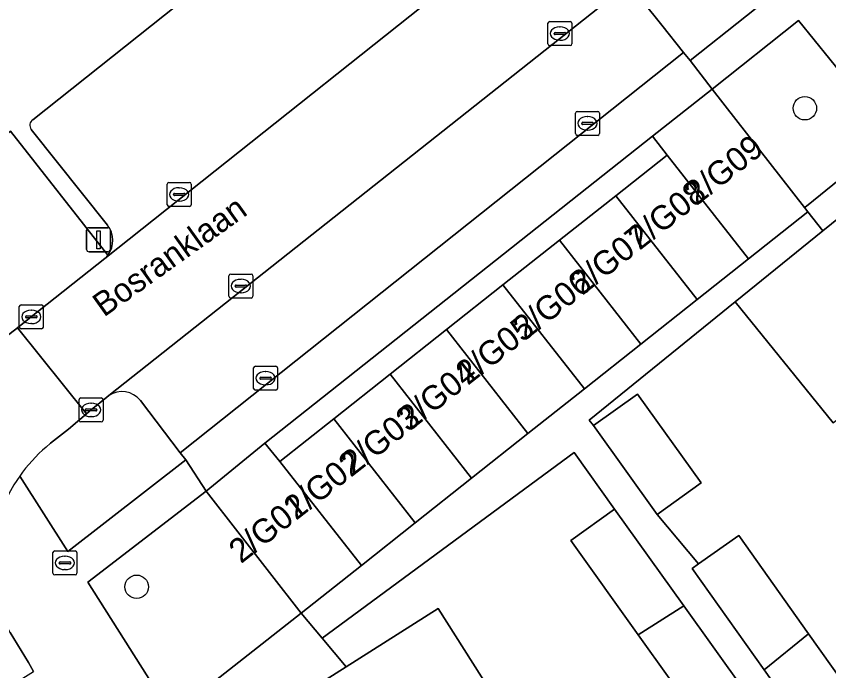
# Model space of a CAD drawing. Extents: x 162344 to 162869, y 381217 to 381818.
# Drawn here: x 162476.05 to 162509.92, y 381652.77 to 381680.06 of the extents above; entities that cross this region are included whole.
import ezdxf

# ---------------------------------------------------------------- set-up
doc = ezdxf.new("R2010")
doc.units = 0
for name, color, linetype in [('IMGEO_Boom', 7, 'Continuous'), ('IMGEO_Brandkraan', 7, 'Continuous'), ('IMGEO_Erf', 7, 'Continuous'), ('IMGEO_Groenvoorziening', 7, 'Continuous'), ('IMGEO_Kolk', 7, 'Continuous'), ('IMGEO_Lichtmast', 7, 'Continuous'), ('IMGEO_Openbare_ruimte_label', 7, 'Continuous'), ('IMGEO_Pand', 7, 'Continuous'), ('IMGEO_Pand_nummerreeks', 7, 'Continuous'), ('IMGEO_Parkeervlak_open', 7, 'Continuous'), ('IMGEO_Rijbaan_lokaal_open', 7, 'Continuous'), ('IMGEO_Voetpad_open', 7, 'Continuous')]:
    doc.layers.add(name, color=color, linetype=linetype)

msp = doc.modelspace()

# ---------------------------------------------------------------- linework, layer by layer
at = {"layer": 'IMGEO_Boom'}
for centre in [(162508.924, 381676.221), (162481.072, 381656.273)]:
    msp.add_circle(centre, 0.489, dxfattribs=at)
at = {"layer": 'IMGEO_Brandkraan'}
for p, q in [((162477.581, 381656.845), (162477.581, 381657.697)), ((162477.656, 381657.771), (162478.508, 381657.771)), ((162478.582, 381657.697), (162478.582, 381656.845)), ((162477.84, 381657.265), (162477.84, 381657.277)), ((162477.883, 381657.314), (162478.281, 381657.314)), ((162478.069, 381657.551), (162478.094, 381657.551)), ((162478.324, 381657.277), (162478.324, 381657.265)), ((162478.278, 381657.228), (162477.88, 381657.228)), ((162478.092, 381656.991), (162478.067, 381656.991)), ((162478.508, 381656.771), (162477.656, 381656.771))]:
    msp.add_line(p, q, dxfattribs=at)
for points in [[(162477.581, 381656.845), (162477.581, 381657.697)], [(162477.656, 381657.771), (162478.508, 381657.771)], [(162478.582, 381657.697), (162478.582, 381656.845)], [(162478.508, 381656.771), (162477.656, 381656.771)]]:
    msp.add_lwpolyline(points, dxfattribs=at)
for centre, radius, start, end in [((162477.658, 381657.695), 0.0765, 91.552, 178.448), ((162477.658, 381657.695), 0.0765, 91.552, 178.448), ((162478.506, 381657.695), 0.0765, 1.552, 88.448), ((162478.506, 381657.695), 0.0765, 1.552, 88.448), ((162477.88, 381657.274), 0.0403, 85.8775, 175.7526), ((162477.877, 381657.264), 0.0366, 178.938, 274.7102), ((162478.281, 381657.271), 0.043, 264.8664, 352.4533), ((162478.285, 381657.276), 0.0386, 1.7309, 96.639), ((162477.658, 381656.847), 0.0765, 181.552, 268.448), ((162477.658, 381656.847), 0.0765, 181.552, 268.448), ((162478.506, 381656.847), 0.0765, 271.552, 358.448), ((162478.506, 381656.847), 0.0765, 271.552, 358.448)]:
    msp.add_arc(centre, radius, start, end, dxfattribs=at)
for centre, major_axis, ratio, start_param, end_param in [((162478.068, 381657.271), (-0.387, 0.002), 0.722429, 4.712389, 7.853982), ((162478.093, 381657.271), (-0.39, 0.002), 0.717154, 1.570796, 4.712389)]:
    msp.add_ellipse(centre, major_axis=major_axis, ratio=ratio, start_param=start_param, end_param=end_param, dxfattribs=at)
at = {"layer": 'IMGEO_Erf'}
msp.add_lwpolyline([(162496.342, 381668.856), (162498.692, 381670.716), (162501.043, 381672.576), (162503.181, 381674.267), (162502.572, 381675.054), (162486.414, 381662.265), (162487.042, 381661.499), (162489.29, 381663.278), (162491.641, 381665.137), (162493.991, 381666.996)], close=True, dxfattribs=at)
for points in [[(162510.099, 381663.114), (162506.026, 381668.154), (162499.933, 381663.224), (162500.114, 381662.996), (162501.945, 381664.309), (162504.599, 381660.606), (162502.768, 381659.294), (162504.496, 381657.227), (162506.17, 381658.416), (162509.083, 381654.315), (162511.58, 381650.8), (162509.855, 381649.575), (162511.736, 381646.935)], [(162510.377, 381642.133), (162507.288, 381646.468), (162509.19, 381647.823), (162506.326, 381651.913), (162504.565, 381650.654), (162501.976, 381654.276), (162499.167, 381658.207), (162500.996, 381659.515), (162499.313, 381661.868), (162488.804, 381654.132), (162489.805, 381652.936), (162493.635, 381655.366), (162496.526, 381650.81), (162500.523, 381644.51), (162504.431, 381638.351), (162507.26, 381633.892), (162509.92, 381629.7), (162513.898, 381623.43)]]:
    msp.add_lwpolyline(points, dxfattribs=at)
at = {"layer": 'IMGEO_Groenvoorziening'}
for points in [[(162502.172, 381680.676), (162502.959, 381679.681), (162503.867, 381678.548), (162504.138, 381678.21), (162508.84, 381681.944)], [(162476.197, 381660.891), (162478.205, 381657.739), (162483.121, 381661.563), (162482.891, 381661.863), (162481.227, 381664.037)], [(162479.911, 381664.241), (162479.827, 381664.177), (162479.173, 381663.648), (162478.985, 381663.489), (162478.231, 381662.85), (162477.479, 381662.26), (162477.304, 381662.098)]]:
    msp.add_lwpolyline(points, dxfattribs=at)
for points in [[(162508.656, 381679.88), (162505.063, 381677.02), (162508.914, 381672.079), (162508.995, 381672.145), (162512.571, 381675.042)], [(162479.74, 381669.953), (162479.875, 381670.101), (162475.807, 381675.259), (162470.329, 381670.872), (162474.439, 381665.794), (162476.099, 381667.062), (162476.682, 381667.526)], [(162483.97, 381660.263), (162479.032, 381656.467), (162482.537, 381650.933), (162487.93, 381655.177)]]:
    msp.add_lwpolyline(points, close=True, dxfattribs=at)
for centre, radius, start, end in [((162480.459, 381663.43), 0.979, 38.3345, 124.0423), ((162481.325, 381657.299), 6.261, 129.9593, 144.9897)]:
    msp.add_arc(centre, radius, start, end, dxfattribs=at)
at = {"layer": 'IMGEO_Kolk'}
for p, q in [((162498.214, 381678.909), (162498.214, 381679.761)), ((162498.289, 381679.835), (162499.141, 381679.835)), ((162498.702, 381679.615), (162498.727, 381679.615)), ((162499.215, 381679.761), (162499.215, 381678.909)), ((162498.473, 381679.329), (162498.473, 381679.341)), ((162498.911, 381679.292), (162498.513, 381679.292)), ((162498.516, 381679.378), (162498.914, 381679.378)), ((162498.957, 381679.341), (162498.957, 381679.329)), ((162498.725, 381679.055), (162498.7, 381679.055)), ((162499.141, 381678.835), (162498.289, 381678.835)), ((162499.363, 381675.165), (162499.363, 381676.017)), ((162499.438, 381676.091), (162500.29, 381676.091)), ((162500.364, 381676.017), (162500.364, 381675.165)), ((162499.622, 381675.585), (162499.622, 381675.597)), ((162500.06, 381675.548), (162499.662, 381675.548)), ((162499.665, 381675.634), (162500.063, 381675.634)), ((162499.851, 381675.871), (162499.876, 381675.871)), ((162500.106, 381675.597), (162500.106, 381675.585)), ((162499.874, 381675.311), (162499.849, 381675.311)), ((162500.29, 381675.091), (162499.438, 381675.091)), ((162482.345, 381672.201), (162482.345, 381673.053)), ((162482.42, 381673.127), (162483.272, 381673.127)), ((162482.833, 381672.907), (162482.858, 381672.907)), ((162483.346, 381673.053), (162483.346, 381672.201)), ((162482.604, 381672.621), (162482.604, 381672.633)), ((162483.042, 381672.584), (162482.644, 381672.584)), ((162482.647, 381672.67), (162483.045, 381672.67)), ((162483.088, 381672.633), (162483.088, 381672.621)), ((162482.856, 381672.347), (162482.831, 381672.347)), ((162483.272, 381672.127), (162482.42, 381672.127)), ((162484.916, 381668.384), (162484.916, 381669.236)), ((162484.991, 381669.31), (162485.843, 381669.31)), ((162485.917, 381669.236), (162485.917, 381668.384)), ((162485.175, 381668.804), (162485.175, 381668.816)), ((162485.613, 381668.767), (162485.215, 381668.767)), ((162485.218, 381668.853), (162485.616, 381668.853)), ((162485.404, 381669.09), (162485.429, 381669.09)), ((162485.659, 381668.816), (162485.659, 381668.804)), ((162485.427, 381668.53), (162485.402, 381668.53)), ((162485.843, 381668.31), (162484.991, 381668.31)), ((162476.181, 381667.1), (162476.181, 381667.952)), ((162476.256, 381668.026), (162477.108, 381668.026)), ((162476.669, 381667.806), (162476.694, 381667.806)), ((162477.182, 381667.952), (162477.182, 381667.1)), ((162476.44, 381667.52), (162476.44, 381667.532)), ((162476.878, 381667.483), (162476.48, 381667.483)), ((162476.483, 381667.569), (162476.881, 381667.569)), ((162476.924, 381667.532), (162476.924, 381667.52)), ((162476.692, 381667.246), (162476.667, 381667.246)), ((162477.108, 381667.026), (162476.256, 381667.026)), ((162485.945, 381664.544), (162485.945, 381665.396)), ((162486.02, 381665.47), (162486.872, 381665.47)), ((162486.946, 381665.396), (162486.946, 381664.544)), ((162486.433, 381665.25), (162486.458, 381665.25)), ((162486.204, 381664.964), (162486.204, 381664.976)), ((162486.642, 381664.927), (162486.244, 381664.927)), ((162486.247, 381665.013), (162486.645, 381665.013)), ((162486.688, 381664.976), (162486.688, 381664.964)), ((162486.872, 381664.47), (162486.02, 381664.47)), ((162486.456, 381664.69), (162486.431, 381664.69)), ((162478.672, 381663.222), (162478.672, 381664.074)), ((162478.747, 381664.148), (162479.599, 381664.148)), ((162479.673, 381664.074), (162479.673, 381663.222)), ((162478.974, 381663.691), (162479.372, 381663.691)), ((162479.16, 381663.928), (162479.185, 381663.928)), ((162478.931, 381663.642), (162478.931, 381663.654)), ((162479.369, 381663.605), (162478.971, 381663.605)), ((162479.183, 381663.368), (162479.158, 381663.368)), ((162479.415, 381663.654), (162479.415, 381663.642)), ((162479.599, 381663.148), (162478.747, 381663.148))]:
    msp.add_line(p, q, dxfattribs=at)
for points in [[(162498.214, 381678.909), (162498.214, 381679.761)], [(162498.289, 381679.835), (162499.141, 381679.835)], [(162499.215, 381679.761), (162499.215, 381678.909)], [(162499.141, 381678.835), (162498.289, 381678.835)], [(162499.363, 381675.165), (162499.363, 381676.017)], [(162499.438, 381676.091), (162500.29, 381676.091)], [(162500.364, 381676.017), (162500.364, 381675.165)], [(162500.29, 381675.091), (162499.438, 381675.091)], [(162482.345, 381672.201), (162482.345, 381673.053)], [(162482.42, 381673.127), (162483.272, 381673.127)], [(162483.346, 381673.053), (162483.346, 381672.201)], [(162483.272, 381672.127), (162482.42, 381672.127)], [(162484.916, 381668.384), (162484.916, 381669.236)], [(162484.991, 381669.31), (162485.843, 381669.31)], [(162485.917, 381669.236), (162485.917, 381668.384)], [(162485.843, 381668.31), (162484.991, 381668.31)], [(162476.181, 381667.1), (162476.181, 381667.952)], [(162476.256, 381668.026), (162477.108, 381668.026)], [(162477.182, 381667.952), (162477.182, 381667.1)], [(162477.108, 381667.026), (162476.256, 381667.026)], [(162485.945, 381664.544), (162485.945, 381665.396)], [(162486.02, 381665.47), (162486.872, 381665.47)], [(162486.946, 381665.396), (162486.946, 381664.544)], [(162486.872, 381664.47), (162486.02, 381664.47)], [(162478.672, 381663.222), (162478.672, 381664.074)], [(162478.747, 381664.148), (162479.599, 381664.148)], [(162479.673, 381664.074), (162479.673, 381663.222)], [(162479.599, 381663.148), (162478.747, 381663.148)]]:
    msp.add_lwpolyline(points, dxfattribs=at)
for centre, radius, start, end in [((162498.291, 381679.759), 0.0765, 91.552, 178.448), ((162498.291, 381679.759), 0.0765, 91.552, 178.448), ((162499.139, 381679.759), 0.0765, 1.552, 88.448), ((162499.139, 381679.759), 0.0765, 1.552, 88.448), ((162498.513, 381679.338), 0.0403, 85.8775, 175.7526), ((162498.51, 381679.328), 0.0366, 178.938, 274.7102), ((162498.914, 381679.335), 0.043, 264.8664, 352.4533), ((162498.918, 381679.34), 0.0386, 1.7309, 96.639), ((162498.291, 381678.911), 0.0765, 181.552, 268.448), ((162498.291, 381678.911), 0.0765, 181.552, 268.448), ((162499.139, 381678.911), 0.0765, 271.552, 358.448), ((162499.139, 381678.911), 0.0765, 271.552, 358.448), ((162499.44, 381676.015), 0.0765, 91.552, 178.448), ((162499.44, 381676.015), 0.0765, 91.552, 178.448), ((162500.288, 381676.015), 0.0765, 1.552, 88.448), ((162500.288, 381676.015), 0.0765, 1.552, 88.448), ((162499.662, 381675.594), 0.0403, 85.8775, 175.7526), ((162499.659, 381675.584), 0.0366, 178.938, 274.7102), ((162500.063, 381675.591), 0.043, 264.8664, 352.4533), ((162500.067, 381675.596), 0.0386, 1.7309, 96.639), ((162499.44, 381675.167), 0.0765, 181.552, 268.448), ((162499.44, 381675.167), 0.0765, 181.552, 268.448), ((162500.288, 381675.167), 0.0765, 271.552, 358.448), ((162500.288, 381675.167), 0.0765, 271.552, 358.448), ((162482.422, 381673.051), 0.0765, 91.552, 178.448), ((162482.422, 381673.051), 0.0765, 91.552, 178.448), ((162483.27, 381673.051), 0.0765, 1.552, 88.448), ((162483.27, 381673.051), 0.0765, 1.552, 88.448), ((162482.644, 381672.63), 0.0403, 85.8775, 175.7526), ((162482.641, 381672.62), 0.0366, 178.938, 274.7102), ((162483.045, 381672.627), 0.043, 264.8664, 352.4533), ((162483.049, 381672.632), 0.0386, 1.7309, 96.639), ((162482.422, 381672.203), 0.0765, 181.552, 268.448), ((162482.422, 381672.203), 0.0765, 181.552, 268.448), ((162483.27, 381672.203), 0.0765, 271.552, 358.448), ((162483.27, 381672.203), 0.0765, 271.552, 358.448), ((162484.993, 381669.234), 0.0765, 91.552, 178.448), ((162484.993, 381669.234), 0.0765, 91.552, 178.448), ((162485.841, 381669.234), 0.0765, 1.552, 88.448), ((162485.841, 381669.234), 0.0765, 1.552, 88.448), ((162485.215, 381668.813), 0.0403, 85.8775, 175.7526), ((162485.212, 381668.803), 0.0366, 178.938, 274.7102), ((162485.616, 381668.81), 0.043, 264.8664, 352.4533), ((162485.62, 381668.815), 0.0386, 1.7309, 96.639), ((162484.993, 381668.386), 0.0765, 181.552, 268.448), ((162484.993, 381668.386), 0.0765, 181.552, 268.448), ((162485.841, 381668.386), 0.0765, 271.552, 358.448), ((162485.841, 381668.386), 0.0765, 271.552, 358.448), ((162476.258, 381667.95), 0.0765, 91.552, 178.448), ((162476.258, 381667.95), 0.0765, 91.552, 178.448), ((162477.106, 381667.95), 0.0765, 1.552, 88.448), ((162477.106, 381667.95), 0.0765, 1.552, 88.448), ((162476.48, 381667.529), 0.0403, 85.8775, 175.7526), ((162476.477, 381667.519), 0.0366, 178.938, 274.7102), ((162476.881, 381667.526), 0.043, 264.8664, 352.4533), ((162476.885, 381667.531), 0.0386, 1.7309, 96.639), ((162476.258, 381667.102), 0.0765, 181.552, 268.448), ((162476.258, 381667.102), 0.0765, 181.552, 268.448), ((162477.106, 381667.102), 0.0765, 271.552, 358.448), ((162477.106, 381667.102), 0.0765, 271.552, 358.448), ((162486.022, 381665.394), 0.0765, 91.552, 178.448), ((162486.022, 381665.394), 0.0765, 91.552, 178.448), ((162486.87, 381665.394), 0.0765, 1.552, 88.448), ((162486.87, 381665.394), 0.0765, 1.552, 88.448), ((162486.244, 381664.973), 0.0403, 85.8775, 175.7526), ((162486.241, 381664.963), 0.0366, 178.938, 274.7102), ((162486.645, 381664.97), 0.043, 264.8664, 352.4533), ((162486.649, 381664.975), 0.0386, 1.7309, 96.639), ((162486.022, 381664.546), 0.0765, 181.552, 268.448), ((162486.022, 381664.546), 0.0765, 181.552, 268.448), ((162486.87, 381664.546), 0.0765, 271.552, 358.448), ((162486.87, 381664.546), 0.0765, 271.552, 358.448), ((162478.749, 381664.072), 0.0765, 91.552, 178.448), ((162478.749, 381664.072), 0.0765, 91.552, 178.448), ((162479.597, 381664.072), 0.0765, 1.552, 88.448), ((162479.597, 381664.072), 0.0765, 1.552, 88.448), ((162478.971, 381663.651), 0.0403, 85.8775, 175.7526), ((162479.376, 381663.653), 0.0386, 1.7309, 96.639), ((162478.968, 381663.641), 0.0366, 178.938, 274.7102), ((162479.372, 381663.648), 0.043, 264.8664, 352.4533), ((162478.749, 381663.224), 0.0765, 181.552, 268.448), ((162478.749, 381663.224), 0.0765, 181.552, 268.448), ((162479.597, 381663.224), 0.0765, 271.552, 358.448), ((162479.597, 381663.224), 0.0765, 271.552, 358.448)]:
    msp.add_arc(centre, radius, start, end, dxfattribs=at)
for centre, major_axis, ratio, start_param, end_param in [((162498.701, 381679.335), (-0.387, 0.002), 0.722429, 4.712389, 7.853982), ((162498.726, 381679.335), (-0.39, 0.002), 0.717154, 1.570796, 4.712389), ((162499.85, 381675.591), (-0.387, 0.002), 0.722429, 4.712389, 7.853982), ((162499.875, 381675.591), (-0.39, 0.002), 0.717154, 1.570796, 4.712389), ((162482.832, 381672.627), (-0.387, 0.002), 0.722429, 4.712389, 7.853982), ((162482.857, 381672.627), (-0.39, 0.002), 0.717154, 1.570796, 4.712389), ((162485.403, 381668.81), (-0.387, 0.002), 0.722429, 4.712389, 7.853982), ((162485.428, 381668.81), (-0.39, 0.002), 0.717154, 1.570796, 4.712389), ((162476.668, 381667.526), (-0.387, 0.002), 0.722429, 4.712389, 7.853982), ((162476.693, 381667.526), (-0.39, 0.002), 0.717154, 1.570796, 4.712389), ((162486.432, 381664.97), (-0.387, 0.002), 0.722429, 4.712389, 7.853982), ((162486.457, 381664.97), (-0.39, 0.002), 0.717154, 1.570796, 4.712389), ((162479.159, 381663.648), (-0.387, 0.002), 0.722429, 4.712389, 7.853982), ((162479.184, 381663.648), (-0.39, 0.002), 0.717154, 1.570796, 4.712389)]:
    msp.add_ellipse(centre, major_axis=major_axis, ratio=ratio, start_param=start_param, end_param=end_param, dxfattribs=at)
at = {"layer": 'IMGEO_Lichtmast'}
for p, q in [((162478.986, 381670.338), (162478.986, 381671.138)), ((162478.986, 381671.138), (162478.986, 381670.338)), ((162479.086, 381671.238), (162479.876, 381671.238)), ((162479.876, 381671.238), (162479.086, 381671.238)), ((162479.976, 381671.138), (162479.976, 381670.338)), ((162479.976, 381670.338), (162479.976, 381671.138)), ((162479.876, 381670.238), (162479.086, 381670.238)), ((162479.086, 381670.238), (162479.876, 381670.238))]:
    msp.add_line(p, q, dxfattribs=at)
msp.add_lwpolyline([(162479.406, 381671.113), (162479.556, 381671.113), (162479.556, 381670.363), (162479.406, 381670.363), (162479.406, 381671.113)], dxfattribs=at)
for centre, start, end in [((162479.086, 381671.138), 90, 180), ((162479.086, 381671.138), 90, 180), ((162479.876, 381671.138), 0, 90), ((162479.876, 381671.138), 360, 90), ((162479.086, 381670.338), 180, 270), ((162479.086, 381670.338), 180, 270), ((162479.876, 381670.338), 270, 0), ((162479.876, 381670.338), 270, 0)]:
    msp.add_arc(centre, 0.1, start, end, dxfattribs=at)
at = {"layer": 'IMGEO_Pand'}
for points in [[(162505.063, 381677.02), (162502.572, 381675.054), (162503.181, 381674.267), (162506.57, 381669.941), (162509.05, 381671.905), (162508.914, 381672.079)], [(162503.181, 381674.267), (162501.043, 381672.576), (162504.433, 381668.248), (162506.57, 381669.941)], [(162512.565, 381673.447), (162509.673, 381671.105), (162506.026, 381668.154), (162510.099, 381663.114), (162516.63, 381668.417)], [(162501.043, 381672.576), (162498.692, 381670.716), (162502.083, 381666.387), (162504.433, 381668.248)], [(162498.692, 381670.716), (162496.342, 381668.856), (162499.734, 381664.527), (162502.083, 381666.387)], [(162496.342, 381668.856), (162493.991, 381666.996), (162497.384, 381662.665), (162499.734, 381664.527)], [(162493.991, 381666.996), (162491.641, 381665.137), (162495.035, 381660.804), (162497.384, 381662.665)], [(162491.641, 381665.137), (162489.29, 381663.278), (162492.686, 381658.944), (162495.035, 381660.804)], [(162502.768, 381659.294), (162504.599, 381660.606), (162501.945, 381664.309), (162500.114, 381662.996)], [(162489.29, 381663.278), (162487.042, 381661.499), (162490.438, 381657.164), (162492.686, 381658.944)], [(162487.042, 381661.499), (162486.414, 381662.265), (162483.97, 381660.263), (162487.93, 381655.177), (162490.438, 381657.164)], [(162501.976, 381654.276), (162503.877, 381655.484), (162500.996, 381659.515), (162499.167, 381658.207)], [(162504.496, 381657.227), (162504.225, 381657.034), (162507.227, 381652.808), (162509.083, 381654.315), (162506.17, 381658.416)], [(162496.526, 381650.81), (162493.635, 381655.366), (162489.805, 381652.936), (162486.625, 381650.919), (162490.785, 381644.361), (162494.289, 381646.589), (162493.022, 381648.583)], [(162503.877, 381655.484), (162501.976, 381654.276), (162504.565, 381650.654), (162506.326, 381651.913), (162506.394, 381651.962)], [(162509.083, 381654.315), (162507.227, 381652.808), (162509.634, 381649.418), (162509.855, 381649.575), (162511.58, 381650.8)]]:
    msp.add_lwpolyline(points, close=True, dxfattribs=at)
at = {"layer": 'IMGEO_Parkeervlak_open'}
for points in [[(162493.274, 381688.892), (162476.739, 381675.744)], [(162479.875, 381670.101), (162479.74, 381669.953), (162498.069, 381684.526)], [(162502.297, 381681.971), (162479.911, 381664.241)], [(162503.867, 381678.548), (162502.959, 381679.681), (162502.172, 381680.676)], [(162481.227, 381664.037), (162482.891, 381661.863), (162503.867, 381678.548)], [(162476.675, 381675.341), (162479.854, 381671.348)]]:
    msp.add_lwpolyline(points, dxfattribs=at)
for centre, radius, start, end in [((162476.904, 381675.511), 0.285, 125.3635, 216.5891), ((162479.061, 381670.711), 1.018, 323.168, 38.7616), ((162480.459, 381663.43), 0.979, 38.3345, 124.0423)]:
    msp.add_arc(centre, radius, start, end, dxfattribs=at)
at = {"layer": 'IMGEO_Rijbaan_lokaal_open'}
for points in [[(162536.476, 381714.949), (162534.376, 381713.298), (162524.911, 381705.794), (162522.199, 381703.639), (162499.727, 381685.849), (162498.226, 381684.626), (162498.069, 381684.526), (162479.74, 381669.953), (162476.682, 381667.526), (162476.099, 381667.062), (162478.985, 381663.489), (162479.173, 381663.648), (162479.827, 381664.177), (162479.911, 381664.241), (162502.297, 381681.971)], [(162465.255, 381666.596), (162464.699, 381667.264), (162461.143, 381664.345), (162464.301, 381660.45), (162472.225, 381650.761), (162472.704, 381650.202), (162476.776, 381652.741), (162476.558, 381653.122), (162475.793, 381654.37)], [(162477.304, 381662.098), (162477.479, 381662.26), (162478.231, 381662.85), (162478.985, 381663.489), (162476.099, 381667.062), (162474.439, 381665.794), (162473.727, 381665.25)]]:
    msp.add_lwpolyline(points, dxfattribs=at)
for centre, radius, start, end in [((162481.325, 381657.299), 6.261, 129.9593, 144.9897), ((162481.323, 381657.3), 6.259, 144.9904, 207.9193)]:
    msp.add_arc(centre, radius, start, end, dxfattribs=at)
at = {"layer": 'IMGEO_Voetpad_open'}
for points in [[(162476.739, 381675.744), (162493.274, 381688.892)], [(162474.743, 381681.955), (162467.639, 381676.112), (162466.808, 381675.428), (162470.329, 381670.872), (162475.807, 381675.259), (162479.875, 381670.101)], [(162508.84, 381681.944), (162504.138, 381678.21), (162505.063, 381677.02), (162508.656, 381679.88), (162512.571, 381675.042), (162508.995, 381672.145), (162508.914, 381672.079), (162509.05, 381671.905), (162509.673, 381671.105), (162512.565, 381673.447), (162513.38, 381674.107), (162571.832, 381602.129), (162570.843, 381601.33), (162571.787, 381600.176), (162573.538, 381598.034), (162573.688, 381597.851), (162577.947, 381592.831), (162582.764, 381586.934), (162583.699, 381585.765), (162585.923, 381586.92), (162579.594, 381594.706), (162576.33, 381598.754)], [(162479.854, 381671.348), (162476.675, 381675.341)], [(162509.634, 381649.418), (162507.227, 381652.808), (162504.225, 381657.034), (162504.496, 381657.227), (162502.768, 381659.294), (162500.114, 381662.996), (162499.933, 381663.224), (162506.026, 381668.154), (162509.673, 381671.105), (162509.05, 381671.905), (162506.57, 381669.941), (162504.433, 381668.248), (162502.083, 381666.387), (162499.734, 381664.527), (162497.384, 381662.665), (162495.035, 381660.804), (162492.686, 381658.944), (162490.438, 381657.164), (162487.93, 381655.177), (162488.804, 381654.132), (162499.313, 381661.868), (162500.996, 381659.515), (162503.877, 381655.484), (162506.394, 381651.962)], [(162536.254, 381572.675), (162534.661, 381575.207), (162533.863, 381576.458), (162531.035, 381574.671), (162500, 381623.471), (162483.717, 381649.074), (162486.625, 381650.919), (162489.805, 381652.936), (162488.804, 381654.132), (162487.93, 381655.177), (162482.537, 381650.933), (162479.032, 381656.467), (162483.97, 381660.263), (162483.121, 381661.563), (162478.205, 381657.739), (162476.197, 381660.891)], [(162475.793, 381654.37), (162476.558, 381653.122), (162476.776, 381652.741)]]:
    msp.add_lwpolyline(points, dxfattribs=at)
msp.add_lwpolyline([(162502.572, 381675.054), (162505.063, 381677.02), (162504.138, 381678.21), (162503.867, 381678.548), (162482.891, 381661.863), (162483.121, 381661.563), (162483.97, 381660.263), (162486.414, 381662.265)], close=True, dxfattribs=at)
for centre, radius, start, end in [((162476.904, 381675.511), 0.285, 125.3635, 216.5891), ((162479.061, 381670.711), 1.018, 323.168, 38.7616), ((162481.323, 381657.3), 6.259, 144.9904, 207.9193)]:
    msp.add_arc(centre, radius, start, end, dxfattribs=at)

# ---------------------------------------------------------------- texts
at = {"layer": 'IMGEO_Openbare_ruimte_label'}
msp.add_text('Bosranklaan', height=1, rotation=35.5976, dxfattribs=at).set_placement((162479.707, 381667.491))
at = {"layer": 'IMGEO_Pand_nummerreeks'}
for s, p in [('2/G09', (162504.415, 381672.145)), ('2/G08', (162502.035, 381670.274)), ('2/G07', (162499.647, 381668.397)), ('2/G06', (162497.261, 381666.522)), ('2/G05', (162494.876, 381664.647)), ('2/G04', (162492.491, 381662.772)), ('2/G03', (162490.105, 381660.897)), ('2/G02', (162487.715, 381659.018)), ('2/G01', (162485.421, 381657.215))]:
    msp.add_text(s, height=1, rotation=38.1704, dxfattribs=at).set_placement(p)

doc.saveas('drawing.dxf')
